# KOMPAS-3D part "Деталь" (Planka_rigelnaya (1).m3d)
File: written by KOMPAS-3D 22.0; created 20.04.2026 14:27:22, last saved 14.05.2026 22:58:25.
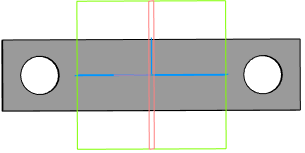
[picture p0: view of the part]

Document properties: Автор: TMK; Полное имя файла: E:\test_kompas\all_v20\Planka_rigelnaya (1).m3d; Организация: TMK

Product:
- Part/product: Деталь
    Масса: 0.134151

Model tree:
1. Эскиз:1
2. Элемент выдавливания:1
     Расстояние 2 = 8
3. Эскиз:2
4. Элемент выдавливания:2
     Расстояние 2 = 10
